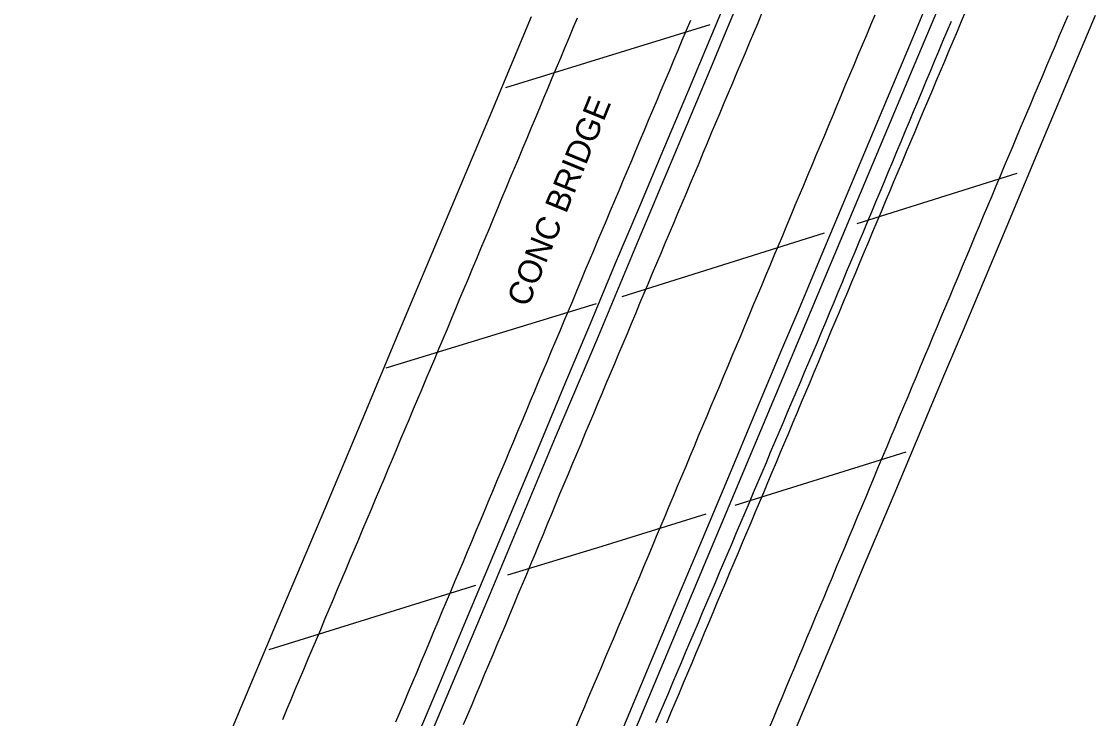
# Model space of a CAD drawing. Extents: x 1948091 to 1975253, y 787267 to 823306.
# Drawn here: x 1968477.1 to 1968724, y 796825.3 to 796985.5 of the extents above; entities that cross this region are included whole.
import ezdxf

# ---------------------------------------------------------------- set-up
doc = ezdxf.new("R2010")
doc.units = 0
for name, color, linetype in [('RD_EX_Bridge', 7, 'Continuous'), ('RD_EX_Bridge_Seam', 7, 'Continuous'), ('RD_EX_Pavement_Markings', 7, 'Continuous'), ('RD_TX_RoadID', 7, 'Continuous')]:
    doc.layers.add(name, color=color, linetype=linetype)

msp = doc.modelspace()

# ---------------------------------------------------------------- linework, layer by layer
at = {"layer": 'RD_EX_Bridge'}
for points in [[(1968650.49, 797010.51), (1968639.02, 796983.23), (1968635.15, 796973.83), (1968626.66, 796953.61), (1968618.9, 796935.19), (1968609.28, 796912.22), (1968599.81, 796889.88), (1968584.86, 796854.03), (1968571.99, 796823.52)], [(1968614.81, 796821.61), (1968621.64, 796837.92), (1968627.18, 796851.11), (1968633.03, 796865.09), (1968640.08, 796881.86), (1968645.41, 796894.53), (1968651.91, 796910.1), (1968655.81, 796919.26), (1968660.16, 796929.71), (1968666.78, 796945.43), (1968674.6, 796964.09), (1968682.46, 796982.81), (1968689.57, 796999.83)], [(1968692.05, 796998.66), (1968682.47, 796975.84), (1968672.15, 796951.28), (1968661.78, 796926.69), (1968652.06, 796903.49), (1968643.2, 796882.34), (1968634.05, 796860.63), (1968625.39, 796839.94), (1968616.1, 796817.77)], [(1968567.3, 796819.24), (1968573.12, 796833.03), (1968578.9, 796846.85), (1968584.72, 796860.7), (1968590.52, 796874.58), (1968596.34, 796888.41), (1968602.13, 796902.27), (1968607.96, 796916.09), (1968613.71, 796929.96), (1968619.26, 796943.09), (1968624.78, 796956.24), (1968630.28, 796969.32), (1968635.79, 796982.45), (1968641.28, 796995.49)], [(1968594.32, 796986.57), (1968584.63, 796963.48), (1968573.3, 796936.54), (1968563.9, 796914.21), (1968555.36, 796893.77), (1968547.01, 796873.9), (1968536.9, 796850.02), (1968527.54, 796827.79), (1968518.84, 796806.97), (1968509.66, 796785.06), (1968500.79, 796764.02), (1968491.38, 796741.62), (1968482.32, 796720.07), (1968473.55, 796699.18), (1968464.61, 796677.9), (1968454.85, 796654.78)], [(1968690.81, 796985.55), (1968689.85, 796983.24), (1968688.88, 796980.94), (1968687.92, 796978.63), (1968686.96, 796976.32), (1968685.99, 796974.02), (1968685.03, 796971.71), (1968684.07, 796969.4), (1968683.11, 796967.09), (1968682.14, 796964.79), (1968681.18, 796962.48), (1968680.22, 796960.17), (1968679.26, 796957.87), (1968678.29, 796955.56), (1968677.33, 796953.25), (1968676.37, 796950.94), (1968675.4, 796948.64), (1968674.44, 796946.33), (1968673.48, 796944.02), (1968672.52, 796941.72), (1968671.55, 796939.41), (1968670.59, 796937.1), (1968669.63, 796934.79), (1968668.67, 796932.49), (1968667.7, 796930.18), (1968666.74, 796927.87), (1968665.78, 796925.56), (1968664.81, 796923.26), (1968663.85, 796920.95), (1968662.89, 796918.64), (1968661.93, 796916.34), (1968660.96, 796914.03), (1968660, 796911.72), (1968659.03, 796909.42), (1968658.05, 796907.12), (1968657.07, 796904.82), (1968656.1, 796902.52), (1968655.12, 796900.21), (1968654.14, 796897.91), (1968653.17, 796895.61), (1968652.19, 796893.31), (1968651.21, 796891.01), (1968650.24, 796888.71), (1968649.26, 796886.41), (1968648.29, 796884.1), (1968647.31, 796881.8), (1968646.33, 796879.5), (1968645.36, 796877.2), (1968644.38, 796874.9), (1968643.4, 796872.6), (1968642.43, 796870.3), (1968641.45, 796867.99), (1968640.47, 796865.69), (1968639.5, 796863.39), (1968638.52, 796861.09), (1968637.54, 796858.79), (1968636.57, 796856.49), (1968635.59, 796854.19), (1968634.62, 796851.88), (1968633.64, 796849.58), (1968632.66, 796847.28), (1968631.69, 796844.98), (1968630.71, 796842.68), (1968629.73, 796840.38), (1968628.76, 796838.08), (1968627.78, 796835.77), (1968626.8, 796833.47), (1968625.83, 796831.17), (1968624.85, 796828.87), (1968623.87, 796826.57), (1968622.9, 796824.27)], [(1968655.28, 796823.32), (1968663.92, 796843.94), (1968670.26, 796859.07), (1968677.7, 796876.75), (1968682.87, 796889.04), (1968689.4, 796904.57), (1968693.65, 796914.68), (1968703.47, 796938.04), (1968712.4, 796959.35), (1968718.87, 796974.81), (1968724.02, 796987.01)]]:
    msp.add_lwpolyline(points, dxfattribs=at)
at = {"layer": 'RD_EX_Bridge_Seam'}
for p, q in [((1968635.39, 796984.77), (1968588.4, 796970.27)), ((1968705.94, 796950.56), (1968669.18, 796939.04)), ((1968661.62, 796936.85), (1968615.13, 796922.21)), ((1968609.23, 796920.64), (1968560.89, 796905.82)), ((1968680.38, 796886.51), (1968641.13, 796874.23)), ((1968581.5, 796855.88), (1968534.02, 796841.07))]:
    msp.add_line(p, q, dxfattribs=at)
msp.add_lwpolyline([(1968634.41, 796872.25), (1968610.52, 796864.8), (1968588.82, 796858.26)], dxfattribs=at)
at = {"layer": 'RD_EX_Pavement_Markings'}
for points in [[(1968647.35, 796987.49), (1968646.38, 796985.18), (1968645.41, 796982.88), (1968644.44, 796980.57), (1968643.47, 796978.27), (1968642.5, 796975.97), (1968641.53, 796973.66), (1968640.56, 796971.36), (1968639.59, 796969.05), (1968638.62, 796966.75), (1968637.65, 796964.44), (1968636.68, 796962.14), (1968635.71, 796959.84), (1968634.74, 796957.53), (1968633.77, 796955.23), (1968632.8, 796952.92), (1968631.83, 796950.62), (1968630.86, 796948.31), (1968629.9, 796946.01), (1968628.93, 796943.7), (1968627.96, 796941.4), (1968626.99, 796939.1), (1968626.02, 796936.79), (1968625.05, 796934.49), (1968624.08, 796932.18), (1968623.11, 796929.88), (1968622.14, 796927.57), (1968621.17, 796925.27), (1968620.2, 796922.96), (1968619.23, 796920.66), (1968618.27, 796918.35), (1968617.3, 796916.05), (1968616.33, 796913.74), (1968615.36, 796911.44), (1968614.39, 796909.14), (1968613.43, 796906.83), (1968612.46, 796904.53), (1968611.49, 796902.22), (1968610.52, 796899.92), (1968609.55, 796897.61), (1968608.59, 796895.31), (1968607.62, 796893), (1968606.65, 796890.7), (1968605.68, 796888.39), (1968604.71, 796886.09), (1968603.75, 796883.78), (1968602.78, 796881.48), (1968601.81, 796879.17), (1968600.84, 796876.87), (1968599.89, 796874.55), (1968598.94, 796872.24), (1968597.99, 796869.93), (1968597.03, 796867.62), (1968596.08, 796865.31), (1968595.13, 796863), (1968594.17, 796860.69), (1968593.2, 796858.38), (1968592.24, 796856.08), (1968591.27, 796853.77), (1968590.3, 796851.47), (1968589.33, 796849.16), (1968588.37, 796846.86), (1968587.4, 796844.55), (1968586.43, 796842.25), (1968585.46, 796839.94), (1968584.5, 796837.64), (1968583.53, 796835.33), (1968582.56, 796833.03), (1968581.59, 796830.72), (1968580.62, 796828.42), (1968579.66, 796826.11), (1968578.69, 796823.81)], [(1968694.13, 796987.84), (1968693.16, 796985.53), (1968692.19, 796983.23), (1968691.22, 796980.92), (1968690.25, 796978.62), (1968689.27, 796976.32), (1968688.3, 796974.02), (1968687.33, 796971.71), (1968686.36, 796969.41), (1968685.38, 796967.11), (1968684.41, 796964.8), (1968683.44, 796962.5), (1968682.46, 796960.2), (1968681.49, 796957.89), (1968680.53, 796955.59), (1968679.56, 796953.28), (1968678.59, 796950.98), (1968677.62, 796948.67), (1968676.66, 796946.37), (1968675.69, 796944.06), (1968674.72, 796941.76), (1968673.75, 796939.45), (1968672.79, 796937.15), (1968671.82, 796934.84), (1968670.85, 796932.54), (1968669.88, 796930.23), (1968668.92, 796927.93), (1968667.95, 796925.62), (1968666.99, 796923.31), (1968666.02, 796921.01), (1968665.06, 796918.7), (1968664.1, 796916.39), (1968663.13, 796914.09), (1968662.17, 796911.78), (1968661.21, 796909.47), (1968660.24, 796907.16), (1968659.28, 796904.86), (1968658.32, 796902.55), (1968657.36, 796900.24), (1968656.39, 796897.94), (1968655.43, 796895.63), (1968654.46, 796893.33), (1968653.49, 796891.02), (1968652.52, 796888.72), (1968651.55, 796886.41), (1968650.58, 796884.11), (1968649.61, 796881.81), (1968648.64, 796879.5), (1968647.67, 796877.2), (1968646.7, 796874.89), (1968645.73, 796872.59), (1968644.76, 796870.29), (1968643.79, 796867.98), (1968642.81, 796865.68), (1968641.84, 796863.37), (1968640.87, 796861.07), (1968639.91, 796858.77), (1968638.94, 796856.46), (1968637.97, 796854.16), (1968637, 796851.85), (1968636.03, 796849.55), (1968635.06, 796847.24), (1968634.09, 796844.94), (1968633.12, 796842.63), (1968632.15, 796840.33), (1968631.19, 796838.02), (1968630.22, 796835.72), (1968629.25, 796833.42), (1968628.28, 796831.11), (1968627.31, 796828.81), (1968626.34, 796826.5), (1968625.37, 796824.2)], [(1968604.87, 796986.32), (1968603.9, 796984.02), (1968602.94, 796981.71), (1968601.97, 796979.4), (1968601.01, 796977.1), (1968600.04, 796974.79), (1968599.08, 796972.48), (1968598.11, 796970.18), (1968597.15, 796967.87), (1968596.18, 796965.57), (1968595.22, 796963.26), (1968594.25, 796960.95), (1968593.29, 796958.65), (1968592.33, 796956.34), (1968591.36, 796954.03), (1968590.4, 796951.73), (1968589.43, 796949.42), (1968588.47, 796947.11), (1968587.5, 796944.81), (1968586.54, 796942.5), (1968585.57, 796940.2), (1968584.61, 796937.89), (1968583.64, 796935.58), (1968582.68, 796933.28), (1968581.71, 796930.97), (1968580.75, 796928.66), (1968579.78, 796926.36), (1968578.82, 796924.05), (1968577.86, 796921.74), (1968576.89, 796919.44), (1968575.93, 796917.13), (1968574.96, 796914.82), (1968574, 796912.52), (1968573.03, 796910.21), (1968572.06, 796907.91), (1968571.09, 796905.6), (1968570.12, 796903.3), (1968569.15, 796901), (1968568.18, 796898.69), (1968567.21, 796896.39), (1968566.23, 796894.09), (1968565.26, 796891.78), (1968564.29, 796889.48), (1968563.32, 796887.18), (1968562.35, 796884.87), (1968561.38, 796882.57), (1968560.41, 796880.27), (1968559.43, 796877.96), (1968558.46, 796875.66), (1968557.49, 796873.35), (1968556.52, 796871.05), (1968555.55, 796868.75), (1968554.58, 796866.44), (1968553.61, 796864.14), (1968552.64, 796861.84), (1968551.66, 796859.53), (1968550.69, 796857.23), (1968549.72, 796854.93), (1968548.75, 796852.62), (1968547.78, 796850.32), (1968546.81, 796848.02), (1968545.84, 796845.71), (1968544.87, 796843.41), (1968543.9, 796841.1), (1968542.92, 796838.8), (1968541.95, 796836.5), (1968540.98, 796834.19), (1968540.01, 796831.89), (1968539.04, 796829.59), (1968538.07, 796827.28), (1968537.1, 796824.98)], [(1968630.9, 796985.79), (1968629.93, 796983.49), (1968628.96, 796981.18), (1968627.99, 796978.88), (1968627.02, 796976.57), (1968626.06, 796974.27), (1968625.09, 796971.96), (1968624.12, 796969.66), (1968623.15, 796967.36), (1968622.18, 796965.05), (1968621.21, 796962.75), (1968620.24, 796960.44), (1968619.27, 796958.14), (1968618.3, 796955.83), (1968617.33, 796953.53), (1968616.36, 796951.23), (1968615.39, 796948.92), (1968614.42, 796946.62), (1968613.45, 796944.31), (1968612.48, 796942.01), (1968611.51, 796939.7), (1968610.54, 796937.4), (1968609.57, 796935.1), (1968608.6, 796932.79), (1968607.63, 796930.49), (1968606.66, 796928.18), (1968605.7, 796925.88), (1968604.73, 796923.57), (1968603.76, 796921.27), (1968602.79, 796918.96), (1968601.82, 796916.66), (1968600.86, 796914.35), (1968599.89, 796912.05), (1968598.92, 796909.74), (1968597.96, 796907.44), (1968596.99, 796905.13), (1968596.02, 796902.82), (1968595.06, 796900.52), (1968594.09, 796898.21), (1968593.13, 796895.91), (1968592.16, 796893.6), (1968591.19, 796891.3), (1968590.23, 796888.99), (1968589.26, 796886.68), (1968588.29, 796884.38), (1968587.33, 796882.07), (1968586.36, 796879.77), (1968585.4, 796877.46), (1968584.43, 796875.16), (1968583.46, 796872.85), (1968582.5, 796870.54), (1968581.53, 796868.24), (1968580.57, 796865.93), (1968579.6, 796863.63), (1968578.63, 796861.32), (1968577.67, 796859.02), (1968576.7, 796856.71), (1968575.73, 796854.4), (1968574.77, 796852.1), (1968573.8, 796849.79), (1968572.83, 796847.49), (1968571.86, 796845.18), (1968570.9, 796842.88), (1968569.93, 796840.57), (1968568.96, 796838.27), (1968567.99, 796835.96), (1968567.03, 796833.66), (1968566.06, 796831.35), (1968565.09, 796829.05), (1968564.12, 796826.74), (1968563.15, 796824.44)], [(1968673.27, 796987.01), (1968672.3, 796984.7), (1968671.34, 796982.4), (1968670.37, 796980.09), (1968669.41, 796977.79), (1968668.44, 796975.48), (1968667.48, 796973.17), (1968666.51, 796970.87), (1968665.55, 796968.56), (1968664.58, 796966.25), (1968663.62, 796963.95), (1968662.65, 796961.64), (1968661.69, 796959.34), (1968660.72, 796957.03), (1968659.76, 796954.72), (1968658.79, 796952.42), (1968657.83, 796950.11), (1968656.86, 796947.81), (1968655.9, 796945.5), (1968654.93, 796943.19), (1968653.97, 796940.89), (1968653, 796938.58), (1968652.04, 796936.27), (1968651.07, 796933.97), (1968650.11, 796931.66), (1968649.14, 796929.36), (1968648.17, 796927.05), (1968647.21, 796924.74), (1968646.24, 796922.44), (1968645.28, 796920.13), (1968644.31, 796917.83), (1968643.34, 796915.52), (1968642.38, 796913.22), (1968641.41, 796910.91), (1968640.45, 796908.6), (1968639.48, 796906.3), (1968638.52, 796903.99), (1968637.55, 796901.69), (1968636.58, 796899.38), (1968635.62, 796897.07), (1968634.65, 796894.77), (1968633.69, 796892.46), (1968632.72, 796890.16), (1968631.75, 796887.85), (1968630.79, 796885.54), (1968629.82, 796883.24), (1968628.86, 796880.93), (1968627.89, 796878.63), (1968626.93, 796876.32), (1968625.96, 796874.02), (1968624.99, 796871.71), (1968624.03, 796869.4), (1968623.06, 796867.1), (1968622.08, 796864.8), (1968621.11, 796862.49), (1968620.14, 796860.19), (1968619.17, 796857.89), (1968618.2, 796855.58), (1968617.23, 796853.28), (1968616.26, 796850.98), (1968615.29, 796848.67), (1968614.31, 796846.37), (1968613.34, 796844.06), (1968612.37, 796841.76), (1968611.4, 796839.46), (1968610.43, 796837.15), (1968609.46, 796834.85), (1968608.49, 796832.55), (1968607.51, 796830.24), (1968606.54, 796827.94), (1968605.57, 796825.64), (1968604.6, 796823.33)], [(1968717.64, 796986.84), (1968716.67, 796984.54), (1968715.7, 796982.23), (1968714.73, 796979.93), (1968713.75, 796977.63), (1968712.78, 796975.32), (1968711.81, 796973.02), (1968710.83, 796970.72), (1968709.86, 796968.41), (1968708.89, 796966.11), (1968707.92, 796963.81), (1968706.94, 796961.51), (1968705.97, 796959.2), (1968705, 796956.9), (1968704.02, 796954.6), (1968703.05, 796952.29), (1968702.09, 796949.99), (1968701.12, 796947.68), (1968700.16, 796945.38), (1968699.19, 796943.07), (1968698.22, 796940.76), (1968697.26, 796938.46), (1968696.29, 796936.15), (1968695.33, 796933.85), (1968694.36, 796931.54), (1968693.4, 796929.23), (1968692.43, 796926.93), (1968691.47, 796924.62), (1968690.5, 796922.31), (1968689.54, 796920.01), (1968688.57, 796917.7), (1968687.61, 796915.4), (1968686.64, 796913.09), (1968685.67, 796910.78), (1968684.71, 796908.48), (1968683.74, 796906.17), (1968682.78, 796903.87), (1968681.81, 796901.56), (1968680.85, 796899.25), (1968679.88, 796896.95), (1968678.92, 796894.64), (1968677.95, 796892.34), (1968676.99, 796890.03), (1968676.02, 796887.72), (1968675.06, 796885.42), (1968674.09, 796883.11), (1968673.12, 796880.81), (1968672.16, 796878.5), (1968671.19, 796876.19), (1968670.23, 796873.89), (1968669.26, 796871.58), (1968668.3, 796869.28), (1968667.33, 796866.97), (1968666.37, 796864.66), (1968665.4, 796862.36), (1968664.44, 796860.05), (1968663.47, 796857.74), (1968662.51, 796855.44), (1968661.54, 796853.13), (1968660.58, 796850.82), (1968659.61, 796848.52), (1968658.65, 796846.21), (1968657.69, 796843.91), (1968656.72, 796841.6), (1968655.76, 796839.29), (1968654.79, 796836.99), (1968653.83, 796834.68), (1968652.86, 796832.37), (1968651.9, 796830.07), (1968650.93, 796827.76), (1968649.97, 796825.45), (1968649, 796823.15)]]:
    msp.add_lwpolyline(points, dxfattribs=at)

# ---------------------------------------------------------------- texts
at = {"layer": 'RD_TX_RoadID'}
msp.add_text('CONC BRIDGE', height=5.4, rotation=67.8596, dxfattribs=at).set_placement((1968593.55, 796919.63))

doc.saveas('drawing.dxf')
